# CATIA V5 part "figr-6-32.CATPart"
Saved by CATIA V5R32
Part number: Part1
Bounding box of the stored display mesh (mm): x -150 to 0, y -70 to 60, z -20 to 40
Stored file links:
  D:\PROJECTS\Project 2022\CATIA V5 6R 2022\Resources\Part Files\c06_catia_v5_6r2022_prt\figr-6-32.CATPart
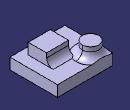
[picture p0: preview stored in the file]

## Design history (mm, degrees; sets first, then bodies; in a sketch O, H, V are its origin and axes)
Body1 (main body)
  Sketch1 on yz-plane, origin (0, 0, 0), H (0, 1, 0), V (0, 0, 1)
    line L1 (-70, 10) -> (60, 10)
    line L2 (60, 10) -> (60, -20)
    line L3 (60, -20) -> (-70, -20)
    line L4 (-70, -20) -> (-70, 10)
    horizontal: L1 H, L3 H
    vertical: L2 V, L4 V
  Pad1: profile Sketch1, direction (-1, 0, 0), length 150
  Sketch2 on face of Pad1 from Sketch1.L1, origin (0, 0, 10), H (1, 0, 0), V (0, 1, 0)
    circle A1 centre (-120, 30) radius 22.3607
  Pad2: profile Sketch2, direction (0, 0, 1), length 30
  Sketch3 on face of Pad1 from Sketch1.L1, origin (0, 0, 10), H (1, 0, 0), V (0, 1, 0)
    point P1 (-90, 0)
    line L1 (-90, 0) -> (-30, 0)
    line L2 (-30, 0) -> (-30, -50)
    line L3 (-30, -50) -> (-90, -50)
    line L4 (-90, -50) -> (-90, 0)
    coincidence: P1 H
    horizontal: L1 H, L3 H
    vertical: L2 V, L4 V
  Pad3: profile Sketch3, direction (0, 0, 1), length 30
  Fillet1: radius 18, on edge [face of Pad1 from Sketch1.L1 | face of Pad3 from Sketch3.L1]; edge [face of Pad1 from Sketch1.L1 | face of Pad2 from Sketch2.A1]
